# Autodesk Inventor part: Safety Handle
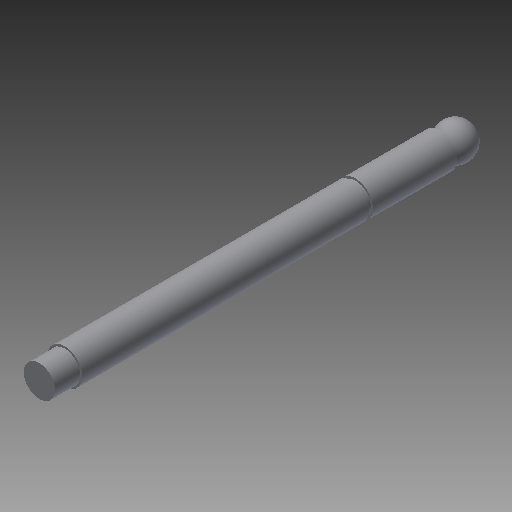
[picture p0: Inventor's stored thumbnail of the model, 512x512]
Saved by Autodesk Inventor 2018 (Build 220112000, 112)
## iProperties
Shininess: 77.0
Length Units: 11269
Angle Units: 11279
Time Units: 11290
Mass Units: 11283
Length Display Precision: 3
Angle Display Precision: 2
Created: 2002-02
Part Number: Safety Handle
Document SubType Name: Modeling
Designer: ***
Density: 1 g/cm^3
Material: Generic
Mass: 54.3914 g
Surface Area: 130.219 cm^2
Volume: 54.3914 cm^3
Appearance: Default
Density: 0.0
Volumn: 0.0
Area: 0.0
PropertySet Name: Model Information
Control State: 0
Master: False
Checked Out: False
Author: ***
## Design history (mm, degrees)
sketch "Sketch1"
  geometry: L1 (0, 205)-(8, 205); L2 (8, 205)-(8, 192); L3 (8, 192)-(9, 192); L4 (9, 192)-(9, 45); L5 (9, 45)-(8, 45); L6 (8, 45)-(8, 43); L7 (8, 43)-(9, 43); L8 (9, 43)-(9, 0); L9 (9, 0)-(0, 0); L10 (0, 0)-(0, 205)
  constraints: 20 end point, 7 parallel, 1 collinear, 1 horizontal, 1 perpendicular
  dimensions: "d0" = 13 distance of L1.end L2.end; "d1" = 2 distance of L4.end L7.end; "d2" = 43 distance of L7.end L8.end; "d3" = 205 distance of L9.end L1.start; "d4" = 16 diameter of L2 L10; "d5" = 18 diameter of L4 L10; "d6" = 16 diameter of L6.end L10
revolve "Revolution1" sketch "Sketch1" stored, may be unused: angle "d7" = 90 deg
sketch "Sketch2"
  geometry: L1 (0, 1)-(0, -17); L2 (-9, 0)-(9, 0) reference; A1 r 9 centre (0, -8) between (0, -17) and (0, 1)
  constraints: 2 end point, 2 point on circle, 1 centre point, 1 midpoint, 1 vertical
  dimensions: "d8" = 9 radius of A1; "d9" = 1 distance from line of L2 L1.start
revolve "Revolution2" sketch "Sketch2" stored, may be unused: angle "d10" = 90 deg
body "Solid1"
